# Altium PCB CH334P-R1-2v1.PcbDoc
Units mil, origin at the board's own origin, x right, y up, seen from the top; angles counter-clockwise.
Board outline 3110.24 x 866.14 mil, 2 copper layers (Top Layer, Bottom Layer); 16 components, 19 nets, 86 pads, 302 vias.
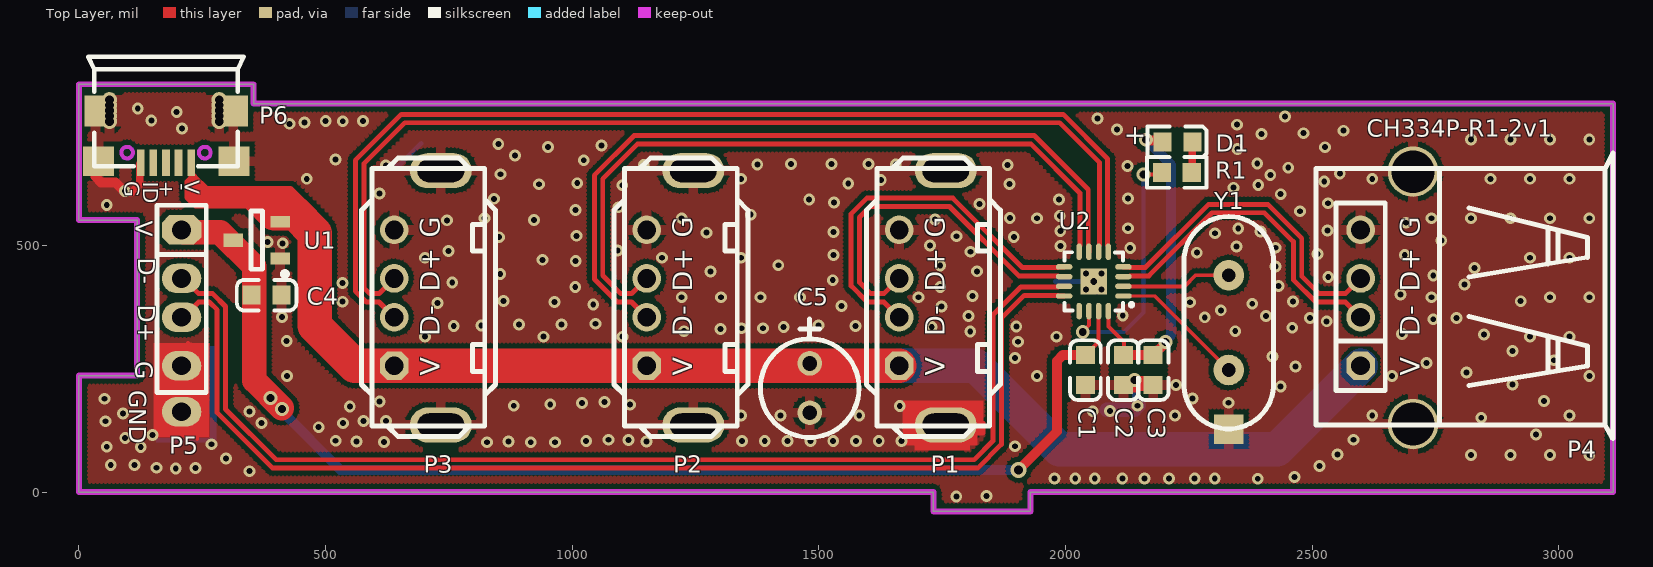
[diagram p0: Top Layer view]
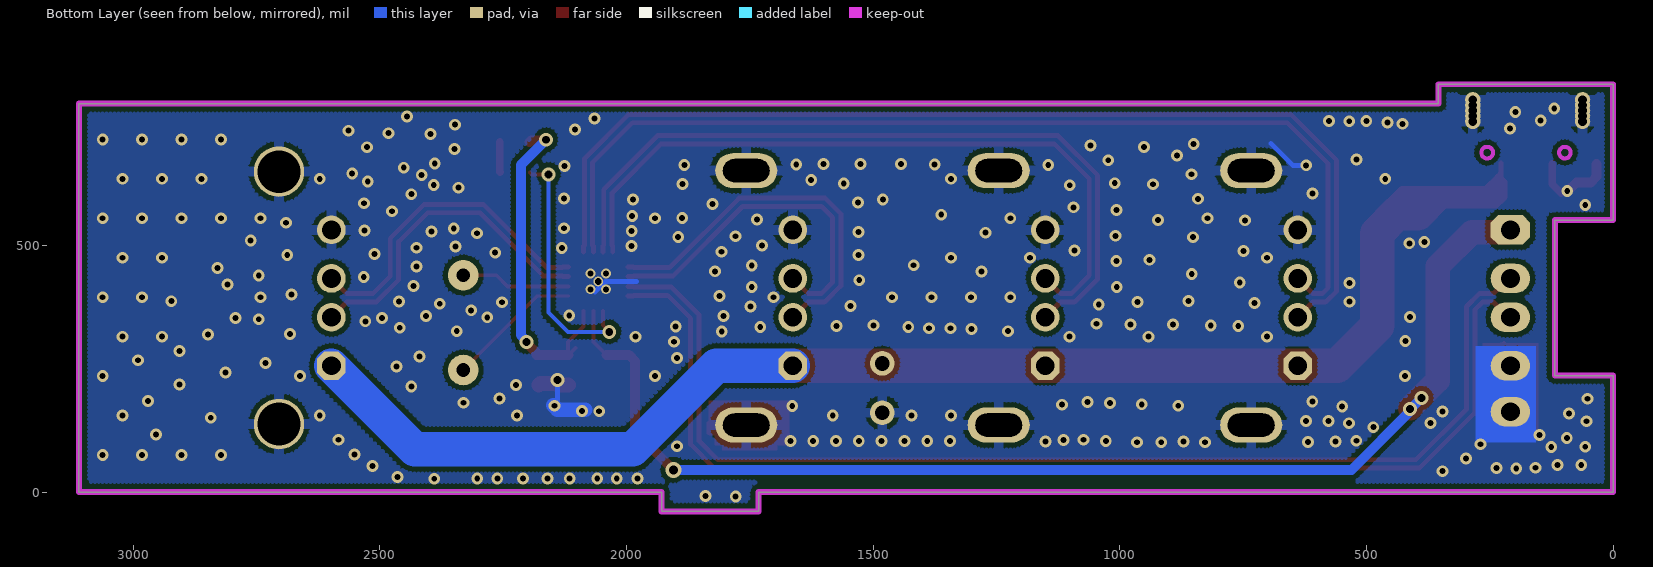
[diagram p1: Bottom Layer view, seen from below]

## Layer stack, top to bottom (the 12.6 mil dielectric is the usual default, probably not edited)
Top Solder: solder mask 0.4, Solder Resist, Dk 3.5
Top Layer: signal copper 1.4
Dielectric 1: dielectric 12.6, FR-4, Dk 4.8
Bottom Layer: signal copper 1.4
Bottom Solder: solder mask 0.4, Solder Resist, Dk 3.5

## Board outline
0,0 0,236.22 118.11,236.22 118.11,551.18 0,551.18 0,826.77 354.33,826.77 354.33,787.4 3110.24,787.4 3110.24,0 1929.13,0 1929.13,-39.37 1732.28,-39.37 1732.28,0

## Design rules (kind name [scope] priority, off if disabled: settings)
Clearance Clearance_1 [InPolygon] p1: gap=10 ignorepadtopadclearanceinfootprint=FALSE
Clearance [All] p2: gap=6 ignorepadtopadclearanceinfootprint=FALSE except(8: Arc-Via Track-Via SMDPad-Via THPad-Via Via-Via Via-Fill Via-Poly Via-Region Via-Hole)
ComponentClearance [All] p1 off: gap=10 collisioncheckmode=3 verticalgap=10 showdistances=FALSE
DiffPairsRouting [All] p1: maxlimit=10 minlimit=7 mostfreqgap=8 toplayer_minwidth=6 toplayer_maxwidth=15 toplayer_prefwidth=8 bottomlayer_minwidth=6 bottomlayer_maxwidth=15 bottomlayer_prefwidth=8 maxuncoupledlength=500
MinimumSolderMaskSliver [All] p1 off: minsoldermaskwidth=10
PolygonConnect PolygonConnect_1 [IsVia] p1: connectstyle=Direct reliefconductorwidth=10 reliefentries=4 polygonreliefangle="90 Angle" airgapwidth=10
PolygonConnect [All] p2: connectstyle=Relief reliefconductorwidth=20 reliefentries=4 polygonreliefangle="90 Angle" airgapwidth=10
RoutingVias [All] p1: holewidth=16 width=28 viastyle="Through Hole" minholewidth=12 minwidth=24 maxholewidth=28 maxwidth=50
SilkToSilkClearance [All] p1 off: silktosilkclearance=10
SilkToSolderMaskClearance [IsPad] p1 off: minsilkscreentomaskgap=10 clearancetoexposedcopper=TRUE
SolderMaskExpansion [All] p1: expansion=4 istentingtop=FALSE
Width [All] p1: maxlimit=100 minlimit=6 preferedwidth=10
25 further rules are at their usual default settings.

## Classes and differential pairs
differential pair UD: +UD_p -UD_n
differential pair UD4: +UD4_p -UD4_n
differential pair UD3: +UD3_p -UD3_n
differential pair UD2: +UD2_p -UD2_n
differential pair UD1: +UD1_p -UD1_n

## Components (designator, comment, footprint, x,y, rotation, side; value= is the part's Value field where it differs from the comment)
C1 "1uF" 0603_C 2040.54,277.54 r270 top
C2 "0.1uF" 0603_C 2117.45,277.54 r270 top
C3 "10uF" 0603_C 2177.9,277.54 r270 top
C4 "10uF" 0603_C 350.19,399.13 r0 top
C5 "220uF" CD0.1 1481.53,260.82 r270 top
D1 "LED" 0603+ 2196.74,709.91 r0 top
P1 "USB" USB2.0-A-F-TH_4P-V_13.7mm 1662.83,255.91 r180 top
P2 "USB" USB2.0-A-F-TH_4P-V_13.7mm 1151.02,255.91 r180 top
P3 "USB" USB2.0-A-F-TH_4P-V_13.7mm 639.21,255.91 r180 top
P4 "USB" USBAF#1 2598.25,255.91 r90 top
P5 "USB" USBAF#2 208.21,531.5 r270 top
P6 "PowerSupply" USBMICROB-02-GXPX-A1T2 227.66,667.45 r180 top
R1 "1K" 0603_R 2225.67,648.06 r0 top
U1 "CH213K" SOT-23-3 407.84,473.36 r90 top
U2 "CH334P" QFN16_3X3 2057.43,426.97 r90 top
Y1 "12M" XT_AT49 2330.98,247.39 r0 top

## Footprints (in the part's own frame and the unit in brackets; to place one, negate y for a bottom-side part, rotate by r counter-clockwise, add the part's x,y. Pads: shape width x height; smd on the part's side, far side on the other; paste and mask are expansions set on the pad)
0603+ [mm]
  rect 0.93x0.98 smd: 1(0,0) 2(1.54,0)
  silkscreen extent -0.76,-0.79 2.27,0.79
0603_C [mm]
  rect 0.93x0.98 smd: 1(0,0) 2(1.54,0)
  silkscreen extent -0.76,-0.79 2.31,0.79
0603_R [mm]
  rect 0.93x0.98 smd: 1(-0.77,0) 2(0.77,0)
  silkscreen extent -1.53,-0.79 1.54,0.79
CD0.1 [mil]
  round 50 hole 30: 1(0,0) 2(100,0)
  silkscreen extent -90,-100 150,100
QFN16_3X3 [mm]
  round 0.508 hole 0.356: 0(0,0)
  rect 1.35x1.35 smd mask+0.051: 0(0,0)
  oval 0.28x0.85 smd mask+0.051: 1(-0.75,-1.526) 2(-0.25,-1.526) 3(0.25,-1.526) 4(0.75,-1.526) 9(0.75,1.526) 10(0.25,1.526) 11(-0.25,1.526) 12(-0.75,1.526)
  oval 0.85x0.28 smd mask+0.051: 5(1.526,-0.75) 6(1.526,-0.25) 7(1.526,0.25) 8(1.526,0.75) 13(-1.526,0.75) 14(-1.526,0.25) 15(-1.526,-0.25) 16(-1.526,-0.75)
  silkscreen extent -1.5,-2.02 1.5,1.5, body extent -1.52,-1.52 1.52,1.52, height 0.25
SOT-23-3 [mm] "SOT-23-3"
  rect 0.6x1 smd: 1(0,0) 2(1.9,0)
  rect 0.7x1 smd: 3(0.95,2.4)
  silkscreen extent -0.93,-0.38 2.45,1.49
USB2.0-A-F-TH_4P-V_13.7mm [mm]
  oval 3.2x1.8 hole 1.2 slot 2.4 at 0 deg: 0(-2.4,3.05) 0(-2.4,-10.05)
  oct 1.473x1.473 hole 0.965: 1(0,0)
  round 1.473 hole 0.965: 2(0,-2.5) 3(0,-4.5) 4(0,-7)
  silkscreen extent -5.21,-10.71 1.69,3.65
USBAF#1 [mm]
  round 2.6 hole 2.2: 0(-3,-2.7) 0(10,-2.7)
  oct 1.473x1.473 hole 0.965: 1(0,0)
  round 1.473 hole 0.965: 2(2.5,0) 3(4.5,0) 4(7,0)
  silkscreen extent -3.75,-12.99 10.95,2.29
USBAF#2 [mm]
  oct 1.524x2.032 hole 0.965: 1(0,0)
  oval 1.524x2.032 hole 0.965: 2(2.5,0) 3(4.5,0) 4(7,0)
  silkscreen extent -1.27,-1.27 8.38,1.27
USBMICROB-02-GXPX-A1T2 [mm]
  rect 1.6x1.5 smd: 0(-2.203,-0.083) 0(4.769,-0.083)
  rect 1.5x1.6 smd: 0(-2.167,-2.675)
  round 0.8 hole 0.45: 0(-1.442,-2.134) 0(-1.442,-3.243) 0(-1.442,-2.966) 0(-1.442,-2.689) 0(-1.442,-2.411) 0(4.208,-2.689) 0(4.208,-2.411) 0(4.208,-2.134) 0(4.208,-3.243) 0(4.208,-2.966)
  rect 1.1x1.6 smd: 0(4.933,-2.675)
  rect 0.4x1.35 smd mask+0.051: 1(0,0) 2(0.65,0) 3(1.3,0) 4(1.95,0) 5(2.6,0)
  Keep-Out Layer circle w0.203: c3.3,-0.525 r0.3
  Keep-Out Layer circle w0.203: c-0.7,-0.525 r0.3
  silkscreen extent -2.7,-5.46 5.3,0.17
XT_AT49 [mil]
  rect 60x60 smd: 0(0.03,-119.99)
  round 62 hole 28: 1(0,0) 2(0,192.13)
  silkscreen extent -91,-119 91,311

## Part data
C1 C2 C3 C4 C5: library part CAP, "Capacitor"
D1: "Typical INFRARED GaAs LED"
P1 P2 P3 P4 P5: "USB Port"
P6: library part MicroUSB, "MicroUSB Port"
R1: library part RES
U1: "Ideal Diode 5V*1A"
U2: "4 ports High-Speed USB MTT Hub"
Y1: library part XTAL, "Crystal Oscillator"

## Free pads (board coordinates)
  oval 80x60 hole 38: ""(208.21,162.81)

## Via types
v1: diameter 24, hole 12, Top Layer to Bottom Layer, tented both sides, 290 vias
v2: diameter 28, hole 16, Top Layer to Bottom Layer, tented both sides, 7 vias
v3: diameter 20, hole 12, Top Layer to Bottom Layer, tented both sides, 4 vias
v4: diameter 32, hole 18, Top Layer to Bottom Layer, tented both sides, 1 vias

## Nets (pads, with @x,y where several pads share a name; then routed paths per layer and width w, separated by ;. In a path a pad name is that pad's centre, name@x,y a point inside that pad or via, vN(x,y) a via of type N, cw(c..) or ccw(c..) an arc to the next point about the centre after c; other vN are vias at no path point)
3V3: C2.1 C3.1 D1.1 U2.16 | length 696.8
  Top Layer w8: U2.16 2086.95,335.95 2118.4,304.51 2118.4,278.5 C2.1 C2.1@2103.14,291.85
  Top Layer w20: C2.1 C3.1@2182.89,277.54 ; v2(2163.57,714.17) 2165.1,712.64 2194.01,712.64 D1.1 ; C3.1 2203.91,303.55 v2(2203.07,304.39)
  Bottom Layer w20: v2(2163.57,714.17) 2214.28,663.46 2214.28,317.76 2203.07,306.55 v2(2203.07,304.39)
5V: C1.1 C4.1 P5.1 U1.3 U2.15 | length 2483.8
  Top Layer w8: C1.1 2067.27,304.28 U2.15
  Top Layer w20: v4(1905,45) 1982.83,122.83 1982.83,265.83 1994.55,277.54 C1.1
  Top Layer w50: P5.1 212.86,526.85 286.16,526.85 355.63,457.38 355.63,226.31 v2@411.49,170.45
  Bottom Layer w20: v2(388.56,190.85) 411.03,168.37 v2(411.49,168.37) 411.49,163.75 530.24,45 v4(1905,45)
GND: C1.2 C2.2 C3.2 C4.2 C5.2 P1.0 P1.4 P2.0 P2.4 P3.0 P3.4 P4.0 P4.4 P5.4 P6.0 P6.5 pad. U1.1 U2.0 Y1.0 | length 1392.9
  Top Layer w8: 220.81,208.41 220.81,302.53 ; 222,112.53 222,206.65 ; 225,112.53 225,206.65 ; 227.09,204.87 227.09,299 ; 230,111.08 230,205.21 ; 233,204.17 233,298.3 ; 234,111.08 234,205.21 ; 240,107.99 240,295.21 ; 1834.11,119.74 1834.11,140.29
  Top Layer w15: 104.84,605.5 123.71,624.36 P6.5@123.71,665.85
  Top Layer w20: P6.0@33.46,665 33.46,639.41 45.12,627.76 74.35,627.76 91.94,610.17 v1(93.02,610.17)
  Top Layer w30: C2.2 v2@2139.96,216.91 ; v2@2139.96,220.06 2174.76,220.06 C3.2
  Bottom Layer w10: v1(622.24,662.42) 649.42,662.42 694,707 ; 1979.67,426.7 2043.17,426.7 2064.06,405.81 ; v1@2083.96,167.06 v1@2083.96,169.37 ; v1@2139.81,167.06 2139.81,212.19
  Bottom Layer w30: v1@2083.96,167.06 2139.81,167.06 v1@2148.69,175.94
  other v1: 1778.73,-8.71 1840.22,-8.03 2389.86,26.95 1977.78,27.84 2019.86,27.84 2059.43,27.84 2115.25,27.84 2160.41,27.84 2210.19,27.84 2262,27.84 2302.63,27.84 2464.24,30.57 345.77,42.29 196.36,47.86 157.58,49.29 236.59,48.81 2514.7,52.91 64.67,55.04 112.56,54.56 298,68.06 2822,75 2902,75 2982,75 3062,75 2551.51,75.81 125.49,91.43 56.53,91.91 1897.91,92.85 269.09,96.97 618.87,101.5 827.57,100.97 916.07,100.97 965.42,100.97 563.05,102.8 870.97,102.68 1150.93,102.68 1344.12,103.19 1390.38,103.19 1436.63,103.19 1482.89,103.19 1529.14,103.19 1575.4,103.19 1621.65,103.19 1667.91,103.19 520.64,104.1 1028.39,103.53 1114.34,105.23 1073.49,106.08 2584.23,106.08 93.89,109.63 149.43,115.38 2953.66,116.98 486.12,131.54 370.18,139.83 535.35,139.58 54.14,143.63 576.89,143.91 622.77,143.91 2842.89,150.73 1342,155 1422,155 1582,155 2222,155 2622,155 3022,155 89.58,159.43 345.61,163.53 2055.45,163.81 2090.38,164.63 549.2,173.34 1664.05,174.13 881.63,174.96 2145.86,174.9 1117.55,177.16 955.63,177.89 1020.11,180.82 2330.39,181.01 1065.53,182.28 609.78,183.72 2970.04,184.47 51.74,189.12 2257.28,189.87 2436.35,213.77 2223.94,217.23 2906.47,218.22 422,235 1942,235 2662,235 3062,235 2813.04,242.58 2466.61,254.53 2732.05,261.79 2990.27,267.24 1897.51,272.07 2419.56,275.03 2906.47,285.71 1903.56,304.77 421.24,305.91 702,315 942,315 1102,315 1982,315 2942,315 3022,315 2848.67,319.45 2681.97,320.55 1226.76,326.1 1807.05,325.77 2344.2,326.16 1300.83,330.59 1343.48,332.09 1386.87,332.09 2459.82,333.02 1428.77,334.33 1729.02,334.29 1900.33,335.84 760.01,336.88 1574.67,336.58 815.69,337.61 1499.1,338.07 891.89,339.81 978.34,339.81 1047.21,341.27 2529.59,346.11 2745.54,350.41 2495.56,353.03 2792.74,353.2 2282.31,354.29 411.44,354.62 1803.79,356.93 2406.72,357.22 2116.12,358.02 2314.9,368.42 1749.02,376.08 1545.74,376.85 1042.82,380.11 2378.73,381.74 727.04,383.04 964.42,385.23 2252.28,384.83 534.43,385.94 2461.54,386.48 861.12,387.43 2922.84,386.94 1222,395 1302,395 1382,395 1462,395 1702,395 2742,395 2982,395 3062,395 1811.48,397.65 2679.08,400.49 1006.25,415.39 1746.14,415.53 2431.86,417.55 2809.11,420.69 534.43,423.5 756.97,424.97 1528.18,429.51 2532.67,435.86 2745.54,439.02 854.15,442.07 1280.14,447.3 1820.84,447.54 2829.34,454.43 2425.93,456.98 1746.14,459.32 1417.86,459.82 1007.16,468.13 939.67,470.84 702,475 1182,475 1342,475 2942,475 3022,475 2687.75,480.44 1529.98,480.68 2511.25,482.86 2266.27,485.27 1807.62,487.2 749.2,488.72 1092.03,489.51 2131.2,494.71 2425.93,495.35 2346.44,497.74 1989.97,498.58 1725.48,499.88 413.18,504.31 382.72,506.75 2761.91,510.3 851.82,516.71 1895.27,517.07 1009,519.49 1779.23,518.54 2303.13,524.72 1272.17,525.84 1529.98,527.32 2395.58,528 1989.61,529.04 2531.26,530.47 2126.77,534.78 2350.37,534.58 2690.64,545.94 746.09,550.91 922.56,551.69 1735.63,552.2 822,555 1222,555 1887.16,555.45 1942,555 2742,555 2822,555 2902,555 2982,555 3062,555 1988.52,559.49 1362.09,562.26 2475.17,569.23 1006.71,571.47 1093.71,577.24 56.52,582.14 1825.74,584.15 2531.95,585.51 1530.58,587.28 1480.46,592.99 1987.07,593.21 841.71,594.45 2126.77,595.3 2436.36,603.88 609.29,605.1 2340.73,617.05 1101.53,621.94 2390.91,622.82 932.67,623.99 1886.44,624.17 1559.66,625.44 1010.25,626.12 2524.65,629.78 1625.68,632.71 462,635 1342,635 2622,635 2862,635 2942,635 3022,635 2415.31,642.81 854.93,644.21 2556.15,645.98 2451.69,657.58 2126,661.19 1145.12,662.73 1882.94,662.7 1375.3,663.89 1655.97,663.89 1443.81,664.72 1525.54,664.72 1600.66,664.72 2388.89,666 1023.41,672.66 520.56,673.84 884.11,682.33 2348.53,695.62 951.33,699.4 2526.2,699.11 1059.64,702.42 850.26,705.62 2822,715 2902,715 2982,715 3062,715 2397.64,725.62 2482.48,727.5 2563.44,732.6 2104.55,734.75 209.17,737.14 2348.1,744.74 426.68,746.52 457.39,749.48 500.31,752.44 534.97,751.72 575.65,752.43 146.87,753.14 2064.71,756.96 2444.72,761.4 198.29,770.28 119.32,777.75
  other v2: 2139.96,227.06
  other v3: 2041.71,411.03 2073.15,411.03 2041.71,442.92 2073.15,442.92
NetD1_2: D1.2 R1.2 | length 62.4
  Top Layer w15: R1.2 2256.68,648.75 2256.68,709.22 D1.2
NetU2_1: U2.1 Y1.1 | length 275.6
  Top Layer w7: U2.1 2180.93,397.45 Y1.1
NetU2_2: U2.2 Y1.2 | length 222.7
  Top Layer w8: U2.2 2241.52,417.13 2263.91,439.52 Y1.2
PGANG: R1.1 U2.14 | length 505.7
  Top Layer w8: v2(2035.04,324.77) 2035.04,325.67 2047.58,338.21 U2.14 ; v2(2158,644) 2191.3,644 R1.1
  Bottom Layer w8: v2(2035.04,324.77) 2119.03,324.77 2158,363.74 v2(2158,644)
RST: U2.13
UD1_n: P1.2 U2.9 | length 773.5
  Top Layer w10: P1.2 1631.96,385.2 1598.32,385.2 1565.48,418.04 1565.48,563.91 1597.33,595.76 1771.89,595.76 1912.49,455.16 1984.5,455.16 1985.84,456.5 U2.9
UD1_p: P1.3 U2.10 | length 717.1
  Top Layer w10: P1.3 1631.96,402.2 1605.36,402.2 1582.48,425.08 1582.48,556.87 1604.37,578.76 1764.85,578.76 1905.45,438.16 1984.5,438.16 1985.84,436.82 U2.10
UD2_n: P2.2 U2.7 | length 1555.1
  Top Layer w10: P2.2 1120.15,385.2 1091.69,385.2 1045,431.89 1045,642.04 1125.69,722.73 1936.76,722.73 2046.24,613.25 2046.24,499.9 2047.58,498.56 U2.7
UD2_p: P2.3 U2.8 | length 1470.6
  Top Layer w10: P2.3 1120.15,402.2 1098.73,402.2 1062,438.93 1062,635 1132.73,705.73 1929.72,705.73 2029.24,606.21 2029.24,499.9 2027.9,498.56 U2.8
UD3_n: P3.2 U2.5 | length 2155.7
  Top Layer w10: P3.2 608.34,385.2 582.57,385.2 560.63,407.14 560.63,672.67 653.57,765.61 1995.3,765.61 2085.61,675.29 2085.61,499.9 2086.95,498.56 U2.5
UD3_p: P3.3 U2.6 | length 2071.2
  Top Layer w10: P3.3 608.34,402.2 589.61,402.2 577.63,414.18 577.63,665.63 660.61,748.61 1988.25,748.61 2068.61,668.25 2068.61,499.9 2067.27,498.56 U2.6
UD4_n: P4.2 U2.3 | length 667.4
  Top Layer w10: U2.3 2129.01,436.82 2130.35,438.16 2169.12,438.16 2297.19,566.23 2403.34,566.23 2462.04,507.54 2462.04,430.28 2507.11,385.2 2567.38,385.2 P4.2
UD4_p: P4.3 U2.4 | length 667.4
  Top Layer w10: U2.4 2129.01,456.5 2130.35,455.16 2162.08,455.16 2290.15,583.23 2410.39,583.23 2479.04,514.58 2479.04,437.32 2514.15,402.2 2567.38,402.2 P4.3
UD_n: P5.2 U2.11 | length 2358.7
  Top Layer w10: P5.2 211.83,433.07 242.7,402.2 271.31,402.2 297.25,376.26 297.25,168.13 399.94,65.44 1814.85,65.44 1853.11,103.71 1853.11,359.35 1909.55,415.79 1984.5,415.79 1985.84,417.13 U2.11
UD_p: P5.3 U2.12 | length 2358.7
  Top Layer w10: P5.3 211.83,354.33 242.7,385.2 264.27,385.2 280.25,369.22 280.25,161.09 392.9,48.44 1821.89,48.44 1870.11,96.67 1870.11,352.31 1916.6,398.79 1984.5,398.79 1985.84,397.45 U2.12
VBUS: C5.1 P1.1 P2.1 P3.1 P4.1 P6.1 U1.2 | length 4587.4
  Top Layer w10: 247.13,591.38 252.13,591.38 ; 252.85,603.63 251.45,605.02 ; 252.85,608.63 252.85,605.02 ; 254.37,584.14 259.37,584.14 ; 273.38,580.94 262.94,591.38 ; 277.03,591.44 268.44,600.02 ; 370.1,562.53 353,579.63 ; 379.44,540.2 340.01,579.63 ; 397.51,582.54 392.72,587.33 332.31,587.33 ; 415.54,594.49 279.95,594.49 274.41,600.02 ; 435.39,569.08 424.84,579.63 353,579.63 ; 473.95,570.9 444.83,600.02 ; 479.2,566.11 440.29,605.02 439.83,605.02 ; 219.15,602.21 241.73,579.63 ; 219.15,602.21 219.15,629.22 226.76,636.83 226.76,666.54 P6.1 P6.1@227.66,646.78 ; 219.15,602.21 219.15,597.21 236.73,579.63 241.73,579.63 ; 227.66,615.85 227.66,619.83 ; 227.66,615.85 227.66,604.47 252.5,579.63 ; 227.66,615.85 238.49,605.02 ; 227.66,619.83 227.66,628.81 ; 227.66,619.83 242.47,605.02 ; 227.66,628.81 P6.1@227.66,646.78 ; 227.66,628.81 251.45,605.02 ; P6.1@227.66,646.78 234.14,640.3 ; 234.14,640.3 258.7,615.74 ; 234.14,640.3 234.14,633.09 258.6,608.63 ; 238.49,605.02 252.13,591.38 ; 238.49,605.02 242.47,605.02 ; 241.73,579.63 252.5,579.63 ; 242.47,605.02 251.45,605.02 ; 242.47,605.02 247.47,600.02 254.3,600.02 ; 251.45,605.02 252.85,605.02 ; 252.13,591.38 262.94,591.38 ; 252.13,591.38 259.37,584.14 ; 252.5,579.63 263.88,579.63 ; 252.85,605.02 257.85,600.02 ; 252.85,605.02 262.21,605.02 ; 254.3,600.02 257.85,600.02 ; 254.3,600.02 262.94,591.38 ; 257.85,600.02 267.21,600.02 ; 257.85,600.02 266.49,591.38 ; 258.6,608.63 262.21,605.02 ; 258.6,608.63 265.81,608.63 ; 258.7,615.74 265.81,608.63 ; 258.7,615.74 429.12,615.74 436.22,608.63 ; 259.37,584.14 263.88,579.63 ; 262.21,605.02 267.21,600.02 ; 262.21,605.02 269.41,605.02 ; 262.94,591.38 266.49,591.38 ; 263.88,579.63 340.01,579.63 ; 265.81,608.63 436.22,608.63 ; 265.81,608.63 269.41,605.02 ; 266.49,591.38 270.54,587.33 332.31,587.33 ; 267.21,600.02 268.44,600.02 ; 268.44,600.02 274.41,600.02 ; 269.41,605.02 439.83,605.02 ; 269.41,605.02 274.41,600.02 ; 274.41,600.02 444.83,600.02 ; 332.31,587.33 335.81,583.83 ; 335.81,583.83 348.8,583.83 353,579.63 ; 335.81,583.83 340.01,579.63 ; 340.01,579.63 353,579.63 ; 436.22,608.63 439.83,605.02 ; 439.83,605.02 444.83,600.02
  Top Layer w70: 395.64,564.85 438.43,564.85 478.43,524.85 478.43,336.73 559.26,255.91 P3.1 P2.1 P1.1
  Bottom Layer w70: P1.1 1818.24,255.91 1987.3,86.84 2429.18,86.84 P4.1
pads on no net: P6.2 P6.3 P6.4

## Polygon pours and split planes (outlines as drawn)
GND on Top Layer "GND" (hatched 90Degree grid 8 track 8, remove dead copper, pour order 0): 0,826.77 0,551.18 118.11,551.18 118.11,236.22 0,236.22 0,0 1732.28,0 1732.28,-39.37 1929.13,-39.37 1929.13,0 3110.24,0 3110.24,787.4 354.33,787.4 354.33,826.77
GND on Bottom Layer "GND" (hatched 90Degree grid 8 track 8, remove dead copper, pour order 1): 0,826.77 0,551.18 118.11,551.18 118.11,236.22 0,236.22 0,0 1732.28,0 1732.28,-39.37 1929.13,-39.37 1929.13,0 3110.24,0 3110.24,787.4 354.33,787.4 354.33,826.77

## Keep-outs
Keep-Out Layer:
  the board outline again, w12

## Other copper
Top Layer:
  rectangle net GND: 1694,84.44 1806,101.7
  rectangle net GND: 1668.7,94.34 1822.2,119.41
  rectangle net GND: 1669.7,115 1834.11,185.26
  rectangle net GND: 151.31,111.08 265.24,302.38
Bottom Layer:
  rectangle net GND: 156.56,100.86 278.7,295.9

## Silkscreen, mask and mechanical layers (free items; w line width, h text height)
Top Overlay:
  text "CH334P-R1-2v1" at 2610.75,720.15 h35
  text "GND" at 102.23,206.83 h35 r270
Mechanical 1:
  lines w10: 0,0 0,236.22 118.11,236.22 118.11,551.18 0,551.18 0,787.4 0,826.77 354.33,826.77 354.33,787.4 3110.24,787.4 3110.24,0 1929.13,0 1929.13,-39.37 1732.28,-39.37 1732.28,0 0,0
